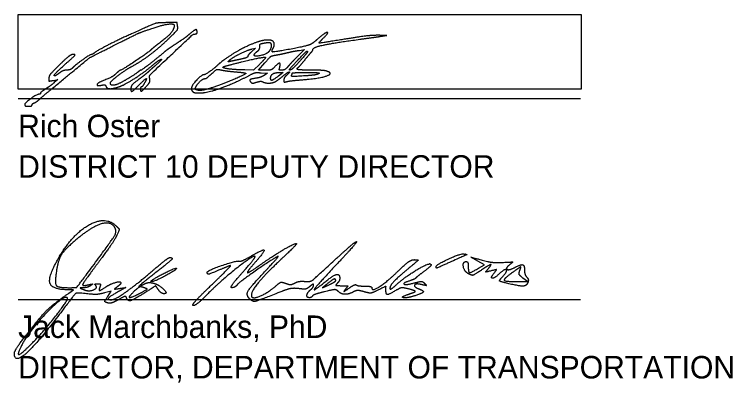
# Model space of a CAD drawing. Extents: x -84548 to 2262448, y -162180 to 525962.
# Drawn here: x 162214 to 185817, y -21058 to -8952 of the extents above; entities that cross this region are included whole.
import ezdxf

# ---------------------------------------------------------------- set-up
doc = ezdxf.new("R2010")
doc.units = 0
doc.layers.add('GM_X_County', color=7, linetype='Continuous')
doc.layers.add('GM_X_Section', color=7, linetype='Continuous')

msp = doc.modelspace()

# ---------------------------------------------------------------- linework, layer by layer
at = {"layer": 'GM_X_County'}
for p, q in [((162338, -11723), (180818, -11723)), ((162338, -18323), (180818, -18323))]:
    msp.add_line(p, q, dxfattribs=at)
msp.add_lwpolyline([(162338, -11406), (162338, -8952), (180839, -8952), (180839, -11406)], close=True, dxfattribs=at)
at = {"layer": 'GM_X_Section'}
for p, q in [((162557, -11919), (162557, -11919)), ((164779, -17241), (164779, -17241)), ((176074, -17245), (176074, -17245)), ((166471, -17935), (166471, -17935)), ((166708, -17715), (166708, -17715)), ((168671, -17868), (168671, -17868)), ((172774, -17704), (172774, -17704)), ((178463, -17806), (178463, -17806))]:
    msp.add_line(p, q, dxfattribs=at)
for points in [[(167579, -9336), (167566, -9221), (167249, -9224)], [(174239, -9678), (174456, -9647), (174257, -9642)], [(170022, -10090), (170140, -10062), (170011, -10179)], [(171579, -10135), (171751, -10110), (171520, -10339)], [(170277, -10584), (170070, -10785), (169788, -10780)], [(170450, -10785), (170234, -10785), (170441, -10550)], [(170326, -10872), (170534, -10884), (170420, -10958)], [(170912, -10864), (171045, -10864), (170890, -10982)], [(163497, -11124), (163646, -11098), (163527, -11197)], [(177467, -17296), (177659, -17182), (177444, -17061)], [(178780, -17737), (179077, -17736), (178926, -17619)], [(172501, -17808), (172345, -17944), (172560, -17840)], [(163999, -18122), (164161, -18010), (163962, -18007)], [(165282, -18227), (165394, -18056), (165174, -18109)]]:
    msp.add_lwpolyline(points, dxfattribs=at)
for points in [[(165626, -9902), (166218, -9604), (166353, -9545), (166734, -9415)], [(167249, -9224), (166919, -9228), (166780, -9271), (166061, -9594)], [(166734, -9415), (167073, -9299), (167467, -9246), (167467, -9317)], [(167467, -9317), (167467, -9443), (167229, -9714), (166917, -9944)], [(167262, -9772), (167547, -9495), (167590, -9435), (167579, -9336)], [(166061, -9594), (165638, -9784), (164920, -10152), (164850, -10214)], [(166813, -10807), (167982, -9700), (168098, -9597), (168170, -9597)], [(167959, -9610), (167874, -9682), (167679, -9822), (167526, -9920)], [(168219, -9538), (168219, -9442), (168127, -9468), (167959, -9610)], [(168170, -9597), (168197, -9597), (168219, -9570), (168219, -9538)], [(172374, -9726), (172568, -9531), (172412, -9559), (172185, -9760)], [(174257, -9642), (174023, -9636), (173580, -9686), (172884, -9799)], [(163467, -11381), (164653, -10399), (164704, -10365), (165626, -9902)], [(166083, -10658), (166367, -10508), (166972, -10053), (167262, -9772)], [(170556, -9795), (170411, -9795), (170085, -9896), (169792, -10032)], [(170279, -10015), (170279, -9944), (170306, -9918), (170402, -9899)], [(170402, -9899), (170470, -9885), (170551, -9874), (170581, -9874)], [(170715, -10071), (170783, -9944), (170696, -9795), (170556, -9795)], [(170581, -9874), (170660, -9874), (170649, -10100), (170566, -10188)], [(172185, -9760), (172084, -9849), (171966, -9936), (171922, -9952)], [(172021, -10114), (172021, -10037), (172668, -9894), (173569, -9770)], [(172884, -9799), (172249, -9902), (172203, -9896), (172374, -9726)], [(173569, -9770), (173818, -9736), (174119, -9695), (174239, -9678)], [(166704, -10119), (166626, -10197), (165745, -10785), (165706, -10785)], [(166917, -9944), (166838, -10002), (166743, -10081), (166704, -10119)], [(167526, -9920), (167374, -10019), (167196, -10145), (167130, -10201)], [(169792, -10032), (169570, -10134), (168997, -10516), (168861, -10652)], [(169289, -10456), (169365, -10378), (169867, -10127), (170022, -10090)], [(170207, -10159), (170246, -10131), (170279, -10066), (170279, -10015)], [(170690, -10180), (170678, -10168), (170689, -10119), (170715, -10071)], [(171922, -9952), (171777, -10005), (170712, -10202), (170690, -10180)], [(171189, -10211), (171309, -10183), (171485, -10148), (171579, -10135)], [(171971, -10198), (171999, -10169), (172021, -10131), (172021, -10114)], [(164103, -10277), (164060, -10284), (163873, -10439), (163687, -10622)], [(164051, -10444), (164198, -10316), (164216, -10259), (164103, -10277)], [(164749, -10270), (164703, -10270), (164230, -10607), (164129, -10712)], [(164850, -10214), (164816, -10245), (164770, -10270), (164749, -10270)], [(167130, -10201), (166895, -10404), (166405, -10785), (166380, -10785)], [(169356, -10597), (169867, -10466), (170446, -10345), (170466, -10365)], [(169883, -10337), (169883, -10358), (169780, -10399), (169655, -10426)], [(170011, -10179), (169940, -10244), (169883, -10315), (169883, -10337)], [(170566, -10188), (170479, -10279), (170052, -10350), (170103, -10265)], [(170103, -10265), (170121, -10235), (170167, -10187), (170207, -10159)], [(170466, -10365), (170476, -10375), (170391, -10474), (170277, -10584)], [(170441, -10550), (170612, -10355), (170677, -10310), (170810, -10289)], [(170810, -10289), (170899, -10275), (171070, -10240), (171189, -10211)], [(171520, -10339), (171392, -10465), (171248, -10616), (171200, -10676)], [(171270, -10785), (171229, -10785), (171342, -10652), (171717, -10260)], [(171847, -10162), (171865, -10180), (171739, -10333), (171461, -10631)], [(171717, -10260), (171778, -10196), (171836, -10152), (171847, -10162)], [(171744, -10468), (171841, -10348), (171944, -10227), (171971, -10198)], [(163523, -10973), (163504, -10954), (163752, -10705), (164051, -10444)], [(166754, -10625), (166830, -10558), (166926, -10485), (166967, -10462)], [(166967, -10462), (167077, -10401), (167010, -10494), (166838, -10644)], [(169066, -10695), (169056, -10684), (169186, -10640), (169356, -10597)], [(169328, -10496), (169239, -10515), (169235, -10511), (169289, -10456)], [(169655, -10426), (169530, -10453), (169383, -10485), (169328, -10496)], [(170935, -10686), (170968, -10555), (170884, -10556), (170760, -10687)], [(171536, -10699), (171552, -10692), (171646, -10588), (171744, -10468)], [(163687, -10622), (163442, -10862), (163349, -10981), (163349, -11052)], [(163938, -10785), (163870, -10785), (163760, -10830), (163681, -10889)], [(164129, -10712), (164090, -10752), (164004, -10785), (163938, -10785)], [(165368, -11207), (165368, -11157), (165874, -10768), (166083, -10658)], [(165706, -10785), (165693, -10785), (165633, -10829), (165575, -10884)], [(165649, -11333), (165845, -11265), (166513, -10837), (166754, -10625)], [(166307, -10825), (166230, -10890), (165977, -11051), (165783, -11159)], [(166380, -10785), (166366, -10785), (166333, -10803), (166307, -10825)], [(166632, -10830), (166595, -10865), (166466, -10968), (166344, -11058)], [(166838, -10644), (166761, -10710), (166668, -10794), (166632, -10830)], [(166663, -11069), (166647, -10988), (166678, -10935), (166813, -10807)], [(168861, -10652), (168781, -10733), (168468, -10943), (168428, -10943)], [(168598, -10992), (168831, -10780), (168889, -10753), (169041, -10786)], [(169041, -10786), (169123, -10803), (169338, -10830), (169520, -10845)], [(169788, -10780), (169497, -10775), (169100, -10728), (169066, -10695)], [(169520, -10845), (169701, -10860), (169835, -10886), (169817, -10901)], [(170760, -10687), (170682, -10768), (170629, -10785), (170450, -10785)], [(171011, -10785), (170924, -10785), (170914, -10772), (170935, -10686)], [(171200, -10676), (171145, -10743), (171072, -10785), (171011, -10785)], [(171023, -10993), (171195, -10854), (171297, -10830), (171150, -10963)], [(171461, -10631), (171382, -10716), (171296, -10785), (171270, -10785)], [(171506, -10749), (171506, -10729), (171520, -10706), (171536, -10699)], [(171932, -10785), (171698, -10785), (171506, -10769), (171506, -10749)], [(171665, -11103), (172252, -11058), (172720, -10883), (172448, -10810)], [(172448, -10810), (172398, -10797), (172166, -10786), (171932, -10785)], [(163349, -11052), (163349, -11144), (163358, -11148), (163497, -11124)], [(163681, -10889), (163606, -10947), (163535, -10985), (163523, -10973)], [(165575, -10884), (165473, -10978), (165397, -11020), (165101, -11146)], [(166344, -11058), (166134, -11213), (166041, -11323), (166041, -11416)], [(166305, -11280), (166508, -11074), (166582, -11050), (166485, -11220)], [(166556, -11314), (166649, -11208), (166677, -11143), (166663, -11069)], [(168428, -10943), (168370, -10943), (168069, -11252), (168041, -11340)], [(168185, -11326), (168236, -11227), (168417, -11066), (168479, -11064)], [(168275, -11537), (168537, -11537), (169378, -11247), (169892, -10979)], [(168479, -11064), (168502, -11063), (168556, -11031), (168598, -10992)], [(169817, -10901), (169767, -10944), (169228, -11176), (168893, -11299)], [(169892, -10979), (170076, -10882), (170159, -10862), (170326, -10872)], [(170153, -11052), (169987, -11074), (169929, -11124), (169993, -11189)], [(170420, -10958), (170358, -10998), (170238, -11041), (170153, -11052)], [(170635, -11048), (170635, -10957), (170774, -10864), (170912, -10864)], [(170890, -10982), (170721, -11110), (170635, -11132), (170635, -11048)], [(170774, -11171), (170817, -11149), (170929, -11069), (171023, -10993)], [(171150, -10963), (171106, -11002), (171071, -11070), (171071, -11112)], [(171719, -10978), (171383, -10999), (171311, -10994), (171327, -10950)], [(171327, -10950), (171339, -10921), (171348, -10890), (171348, -10881)], [(171348, -10881), (171348, -10872), (171557, -10865), (171813, -10865)], [(172204, -10910), (172164, -10933), (171945, -10964), (171719, -10978)], [(171813, -10865), (172167, -10866), (172261, -10877), (172204, -10910)], [(163527, -11197), (163461, -11252), (163332, -11346), (163240, -11405)], [(165101, -11146), (164936, -11216), (164925, -11316), (165086, -11281)], [(165086, -11281), (165169, -11263), (165206, -11273), (165223, -11317)], [(165223, -11317), (165252, -11392), (165457, -11399), (165649, -11333)], [(165783, -11159), (165587, -11269), (165368, -11294), (165368, -11207)], [(166041, -11416), (166041, -11501), (166134, -11454), (166305, -11280)], [(166358, -11399), (166358, -11495), (166421, -11468), (166556, -11314)], [(166485, -11220), (166448, -11285), (166404, -11339), (166388, -11339)], [(168190, -11432), (168153, -11417), (168151, -11392), (168185, -11326)], [(168893, -11299), (168590, -11410), (168279, -11469), (168190, -11432)], [(169993, -11189), (170021, -11216), (170079, -11214), (170175, -11182)], [(170175, -11182), (170253, -11157), (170337, -11148), (170362, -11164)], [(170362, -11164), (170437, -11210), (170688, -11214), (170774, -11171)], [(171071, -11112), (171071, -11175), (171088, -11185), (171160, -11163)], [(171160, -11163), (171209, -11148), (171436, -11121), (171665, -11103)], [(163071, -11545), (163071, -11563), (163053, -11577), (163031, -11577)], [(163032, -11750), (163086, -11700), (163282, -11535), (163467, -11381)], [(163240, -11405), (163147, -11465), (163071, -11528), (163071, -11545)], [(166388, -11339), (166372, -11339), (166358, -11366), (166358, -11399)], [(168041, -11340), (168027, -11385), (168036, -11448), (168063, -11480)], [(168063, -11480), (168090, -11513), (168179, -11537), (168275, -11537)], [(163031, -11577), (162956, -11577), (162557, -11865), (162557, -11919)], [(162863, -11865), (162902, -11851), (162977, -11799), (163032, -11750)], [(162557, -11919), (162557, -11952), (162602, -11973), (162675, -11973)], [(162675, -11973), (162741, -11973), (162794, -11955), (162794, -11932)], [(162794, -11932), (162794, -11910), (162825, -11880), (162863, -11865)], [(163663, -16973), (164119, -16179), (165217, -15566), (165564, -15913)], [(165517, -15961), (165380, -15739), (164714, -15957), (164211, -16388)], [(164779, -17241), (165420, -16378), (165591, -16081), (165517, -15961)], [(165564, -15913), (165663, -16012), (165663, -16038), (165567, -16241)], [(165567, -16241), (165509, -16363), (165236, -16762), (164960, -17128)], [(164211, -16388), (163859, -16689), (163654, -17027), (163595, -17404)], [(170283, -17192), (170708, -16893), (171401, -16485), (171484, -16485)], [(171484, -16485), (171510, -16485), (171292, -16710), (171000, -16985)], [(172681, -17084), (173077, -16719), (173426, -16420), (173456, -16420)], [(173456, -16420), (173487, -16420), (173212, -16737), (172846, -17126)], [(169972, -16909), (170387, -16666), (170452, -16736), (170139, -17091)], [(163962, -18007), (163444, -17998), (163321, -17569), (163663, -16973)], [(166779, -17361), (167045, -17134), (167286, -16949), (167313, -16948)], [(167313, -16948), (167444, -16946), (167321, -17080), (166867, -17436)], [(170120, -16911), (170069, -16860), (168962, -17741), (168550, -18160)], [(170860, -16913), (170601, -17060), (169607, -17758), (169537, -17842)], [(169625, -17064), (169654, -17073), (169810, -17004), (169972, -16909)], [(169709, -17441), (169953, -17168), (170138, -16929), (170120, -16911)], [(171000, -16985), (170474, -17480), (170002, -18051), (170002, -18194)], [(170516, -17330), (170760, -17070), (170915, -16882), (170860, -16913)], [(176074, -17245), (176074, -17180), (176881, -16808), (176981, -16828)], [(176981, -16828), (177090, -16849), (177094, -16847), (176452, -17136)], [(177444, -17061), (177218, -16934), (177213, -16933), (177757, -17073)], [(164960, -17128), (164684, -17494), (164458, -17814), (164458, -17840)], [(168551, -17426), (168553, -17370), (169542, -17036), (169625, -17064)], [(168671, -17868), (169046, -17507), (169338, -17211), (169320, -17211)], [(169320, -17211), (169302, -17211), (169149, -17271), (168979, -17343)], [(170139, -17091), (169991, -17259), (169870, -17416), (169870, -17439)], [(169870, -17439), (169870, -17463), (170056, -17351), (170283, -17192)], [(171757, -17730), (171934, -17745), (172058, -17658), (172681, -17084)], [(172846, -17126), (172162, -17852), (171993, -18102), (172426, -17744)], [(174738, -17863), (175021, -17605), (175797, -17130), (175886, -17159)], [(174837, -17381), (175075, -17150), (175272, -17014), (175365, -17016)], [(175365, -17016), (175493, -17019), (175473, -17052), (175216, -17264)], [(175886, -17159), (175930, -17174), (175850, -17273), (175707, -17380)], [(176452, -17136), (176122, -17284), (176074, -17298), (176074, -17245)], [(177136, -17478), (176996, -17403), (176938, -17079), (177064, -17079)], [(177064, -17079), (177101, -17079), (177130, -17153), (177130, -17244)], [(177782, -17321), (177911, -17165), (177827, -17185), (177530, -17381)], [(177757, -17073), (177866, -17101), (178104, -17115), (178285, -17105)], [(178285, -17105), (178575, -17089), (178601, -17097), (178496, -17176)], [(178496, -17176), (178344, -17289), (178465, -17375), (178643, -17280)], [(178643, -17280), (178855, -17167), (178978, -17197), (178978, -17363)], [(163595, -17404), (163535, -17791), (163648, -17937), (164007, -17937)], [(164007, -17937), (164254, -17937), (164278, -17915), (164779, -17241)], [(165399, -18333), (165521, -18333), (166186, -17864), (166779, -17361)], [(166867, -17436), (166375, -17821), (166262, -17935), (166494, -17811)], [(166708, -17715), (166815, -17621), (167513, -17274), (167540, -17301)], [(167540, -17301), (167572, -17333), (166820, -17739), (166726, -17739)], [(168979, -17343), (168649, -17485), (168550, -17504), (168551, -17426)], [(169361, -17937), (169307, -17937), (169460, -17719), (169709, -17441)], [(169951, -18310), (169818, -18177), (169970, -17912), (170516, -17330)], [(173962, -17945), (173962, -18066), (174465, -17741), (174837, -17381)], [(175216, -17264), (174825, -17585), (174556, -17868), (174556, -17957)], [(175707, -17380), (175564, -17486), (175432, -17592), (175414, -17614)], [(177130, -17244), (177130, -17439), (177206, -17450), (177467, -17296)], [(177530, -17381), (177319, -17521), (177249, -17539), (177136, -17478)], [(177884, -17383), (177710, -17426), (177700, -17421), (177782, -17321)], [(177990, -17440), (178068, -17347), (178056, -17340), (177884, -17383)], [(178142, -17486), (177974, -17644), (177852, -17607), (177990, -17440)], [(178275, -17553), (178436, -17375), (178321, -17317), (178142, -17486)], [(178821, -17379), (178874, -17243), (178830, -17259), (178500, -17500)], [(178926, -17619), (178818, -17537), (178788, -17467), (178821, -17379)], [(178978, -17363), (178978, -17446), (179012, -17548), (179053, -17590)], [(172426, -17744), (172682, -17533), (172906, -17479), (172906, -17627)], [(172774, -17704), (172774, -17633), (172647, -17682), (172501, -17808)], [(172906, -17627), (172906, -17674), (172871, -17748), (172827, -17792)], [(175233, -17702), (174971, -17783), (175074, -17856), (175348, -17782)], [(175414, -17614), (175396, -17637), (175315, -17676), (175233, -17702)], [(178463, -17806), (178175, -17738), (178144, -17697), (178275, -17553)], [(178500, -17500), (178274, -17664), (178361, -17737), (178780, -17737)], [(179053, -17590), (179094, -17631), (179110, -17711), (179088, -17768)], [(164458, -17840), (164458, -17865), (164540, -17867), (164640, -17843)], [(164722, -17868), (164668, -17905), (164564, -17937), (164491, -17940)], [(164513, -18007), (164671, -18071), (164968, -17941), (164876, -17849)], [(164640, -17843), (164774, -17812), (164796, -17818), (164722, -17868)], [(164876, -17849), (164852, -17825), (164885, -17805), (164949, -17805)], [(164949, -17805), (165026, -17805), (165053, -17839), (165028, -17904)], [(165028, -17904), (164981, -18027), (165049, -18030), (165219, -17914)], [(165219, -17914), (165372, -17810), (165712, -17717), (165712, -17780)], [(165598, -17907), (165498, -17980), (165509, -17987), (165681, -17961)], [(165712, -17780), (165712, -17804), (165661, -17861), (165598, -17907)], [(165681, -17961), (165875, -17932), (165874, -17933), (165634, -18066)], [(166471, -17935), (166380, -17902), (166293, -17929), (166191, -18022)], [(166323, -18127), (166568, -18002), (166587, -17977), (166471, -17935)], [(166494, -17811), (166560, -17775), (166687, -17764), (166774, -17786)], [(166949, -18005), (166860, -17878), (166849, -17880), (166502, -18104)], [(166726, -17739), (166701, -17739), (166693, -17728), (166708, -17715)], [(166774, -17786), (166965, -17835), (167273, -18135), (167132, -18135)], [(168088, -18527), (168034, -18526), (168296, -18230), (168671, -17868)], [(169537, -17842), (169494, -17894), (169415, -17937), (169361, -17937)], [(170098, -18267), (170212, -18267), (170642, -18028), (170834, -17858)], [(170834, -17858), (170941, -17763), (171009, -17749), (171134, -17796)], [(171134, -17796), (171241, -17837), (171340, -17833), (171425, -17786)], [(171425, -17786), (171495, -17746), (171645, -17721), (171757, -17730)], [(171929, -17893), (171846, -17967), (171734, -17991), (171562, -17969)], [(172048, -17853), (172048, -17815), (171995, -17833), (171929, -17893)], [(171949, -18003), (172004, -17958), (172048, -17890), (172048, -17853)], [(172560, -17840), (172678, -17783), (172774, -17722), (172774, -17704)], [(172827, -17792), (172766, -17854), (172797, -17871), (172967, -17871)], [(172967, -17871), (173165, -17871), (173178, -17882), (173096, -17984)], [(173211, -17953), (173324, -17874), (173433, -17826), (173454, -17847)], [(173454, -17847), (173475, -17867), (173597, -17884), (173727, -17884)], [(173727, -17884), (173856, -17884), (173962, -17912), (173962, -17945)], [(174424, -18011), (174424, -17891), (174419, -17891), (174175, -18011)], [(174556, -17957), (174556, -17996), (174638, -17954), (174738, -17863)], [(175191, -17985), (174986, -17933), (174897, -17941), (174751, -18027)], [(175348, -17782), (175550, -17728), (175631, -17732), (175694, -17796)], [(175596, -17836), (175402, -17788), (175332, -17910), (175513, -17979)], [(175694, -17796), (175761, -17864), (175743, -17872), (175596, -17836)], [(179088, -17768), (179045, -17879), (178828, -17892), (178463, -17806)], [(162674, -19401), (163084, -18870), (163507, -18462), (163999, -18122)], [(164428, -18122), (164252, -18104), (164190, -18159), (163785, -18696)], [(164491, -17940), (164373, -17945), (164375, -17952), (164513, -18007)], [(165174, -18109), (164961, -18161), (164843, -18163), (164428, -18122)], [(165634, -18066), (165364, -18215), (165260, -18333), (165399, -18333)], [(166502, -18104), (166138, -18338), (165940, -18390), (165897, -18261)], [(166191, -18022), (165957, -18236), (166017, -18283), (166323, -18127)], [(167132, -18135), (167081, -18135), (166999, -18077), (166949, -18005)], [(168550, -18160), (168351, -18363), (168143, -18528), (168088, -18527)], [(171005, -18059), (170234, -18364), (170049, -18408), (169951, -18310)], [(171562, -17969), (171408, -17949), (171198, -17983), (171005, -18059)], [(171912, -18267), (171815, -18267), (171840, -18094), (171949, -18003)], [(172410, -18069), (172208, -18118), (172027, -18182), (172008, -18212)], [(172856, -18058), (172797, -17999), (172691, -18002), (172410, -18069)], [(173364, -18071), (173202, -18158), (172949, -18152), (172856, -18058)], [(173096, -17984), (173032, -18063), (173067, -18054), (173211, -17953)], [(173705, -18071), (173563, -18030), (173441, -18030), (173364, -18071)], [(174175, -18011), (173978, -18109), (173880, -18121), (173705, -18071)], [(174751, -18027), (174514, -18168), (174424, -18164), (174424, -18011)], [(175381, -18201), (175135, -18283), (174885, -18252), (175117, -18170)], [(175117, -18170), (175190, -18144), (175294, -18106), (175348, -18087)], [(175348, -18087), (175409, -18065), (175347, -18025), (175191, -17985)], [(175513, -17979), (175675, -18041), (175628, -18120), (175381, -18201)], [(163962, -18276), (163851, -18166), (162697, -19358), (162453, -19835)], [(162823, -19736), (163180, -19371), (164002, -18317), (163962, -18276)], [(165276, -18438), (165180, -18402), (165180, -18382), (165282, -18227)], [(165627, -18334), (165492, -18414), (165334, -18461), (165276, -18438)], [(165897, -18261), (165882, -18216), (165781, -18243), (165627, -18334)], [(170002, -18194), (170002, -18234), (170045, -18267), (170098, -18267)], [(172008, -18212), (171990, -18243), (171947, -18267), (171912, -18267)], [(163785, -18696), (162980, -19763), (162214, -20442), (162214, -20089)], [(162214, -20089), (162214, -20038), (162421, -19728), (162674, -19401)], [(162453, -19835), (162288, -20157), (162455, -20112), (162823, -19736)]]:
    msp.add_open_spline(points, degree=2, dxfattribs=at)

# ---------------------------------------------------------------- texts
for s, p in [('Rich Oster', (162338, -12990)), ('DISTRICT 10 DEPUTY DIRECTOR', (162338, -14321)), ('Jack Marchbanks, PhD', (162338, -19590)), ('DIRECTOR, DEPARTMENT OF TRANSPORTATION', (162338, -20921))]:
    msp.add_text(s, height=739.2, dxfattribs=at).set_placement(p)

doc.saveas('drawing.dxf')
